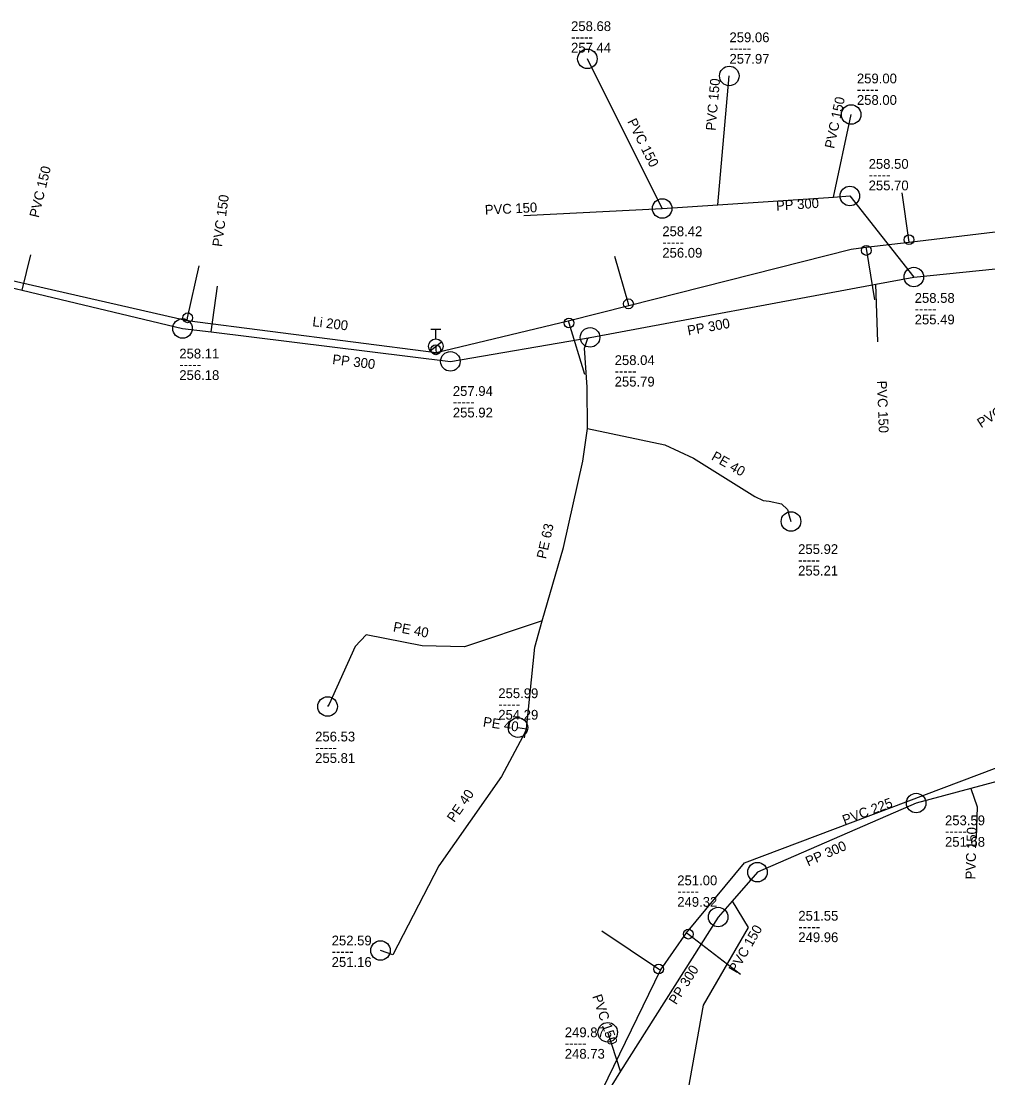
# Model space of a CAD drawing. Extents: x -771681 to -770485, y -1050143 to -1049574.
# Drawn here: x -770751.8 to -770653, y -1050034.6 to -1049926.5 of the extents above; entities that cross this region are included whole.
import ezdxf

# ---------------------------------------------------------------- set-up
doc = ezdxf.new("R2010")
doc.units = 0
doc.layers.add('Level 0', color=7, linetype='Continuous')

msp = doc.modelspace()

# ---------------------------------------------------------------- linework, layer by layer
at = {"layer": 'Level 0'}
for p, q in [((-770686.27, -1049945.68), (-770693.92, -1049930.37)), ((-770680.57, -1049945.3), (-770679.41, -1049932.12)), ((-770668.75, -1049944.51), (-770666.95, -1049936.07)), ((-770661.04, -1049948.87), (-770661.73, -1049944.09)), ((-770686.27, -1049945.68), (-770680.57, -1049945.3)), ((-770680.57, -1049945.3), (-770668.75, -1049944.51)), ((-770668.75, -1049944.51), (-770667.08, -1049944.4)), ((-770667.08, -1049944.4), (-770660.54, -1049952.69)), ((-770700.43, -1049946.39), (-770686.27, -1049945.68)), ((-770661, -1049949.12), (-770650.48, -1049947.87)), ((-770666.94, -1049949.83), (-770665.44, -1049949.65)), ((-770665.44, -1049949.65), (-770661, -1049949.12)), ((-770665.44, -1049949.65), (-770665.39, -1049949.97)), ((-770661, -1049949.12), (-770661.04, -1049948.87)), ((-770751.73, -1049954.03), (-770750.85, -1049950.41)), ((-770689.72, -1049955.43), (-770691.12, -1049950.59)), ((-770689.67, -1049955.59), (-770666.94, -1049949.83)), ((-770665.39, -1049949.97), (-770664.55, -1049955.01)), ((-770734.8, -1049956.86), (-770733.62, -1049951.55)), ((-770660.54, -1049952.69), (-770648.08, -1049951.45)), ((-770753.04, -1049952.96), (-770734.86, -1049957.12)), ((-770664.43, -1049953.41), (-770660.54, -1049952.69)), ((-770752.89, -1049953.75), (-770751.73, -1049954.03)), ((-770751.73, -1049954.03), (-770735.32, -1049957.95)), ((-770732.39, -1049958.31), (-770731.76, -1049953.63)), ((-770693.65, -1049958.86), (-770664.43, -1049953.41)), ((-770664.21, -1049959.33), (-770664.43, -1049953.41)), ((-770695.88, -1049957.16), (-770689.67, -1049955.59)), ((-770689.67, -1049955.59), (-770689.72, -1049955.43)), ((-770734.86, -1049957.12), (-770734.8, -1049956.86)), ((-770734.86, -1049957.12), (-770709.39, -1049960.4)), ((-770709.39, -1049960.4), (-770695.88, -1049957.16)), ((-770695.88, -1049957.16), (-770695.81, -1049957.39)), ((-770735.32, -1049957.95), (-770732.39, -1049958.31)), ((-770732.39, -1049958.31), (-770707.93, -1049961.32)), ((-770709.92, -1049958.02), (-770708.92, -1049958.02)), ((-770709.42, -1049959.02), (-770709.42, -1049958.02)), ((-770695.81, -1049957.39), (-770694.21, -1049962.61)), ((-770710.01, -1049960.23), (-770708.83, -1049959.31)), ((-770707.93, -1049961.32), (-770693.65, -1049958.86)), ((-770694.22, -1049959.98), (-770693.86, -1049958.95)), ((-770693.86, -1049958.95), (-770693.65, -1049958.86)), ((-770709.42, -1049959.77), (-770709.42, -1049960.13)), ((-770709.42, -1049960.13), (-770709.39, -1049960.4)), ((-770693.94, -1049963.95), (-770694.22, -1049959.98)), ((-770693.92, -1049968.17), (-770693.94, -1049963.95)), ((-770694.4, -1049971.53), (-770693.92, -1049968.17)), ((-770693.92, -1049968.17), (-770686, -1049969.86)), ((-770686, -1049969.86), (-770683.06, -1049971.22)), ((-770683.06, -1049971.22), (-770676.81, -1049975.12)), ((-770696.37, -1049980.37), (-770694.4, -1049971.53)), ((-770676.81, -1049975.12), (-770675.95, -1049975.56)), ((-770675.95, -1049975.56), (-770675.34, -1049975.63)), ((-770675.34, -1049975.63), (-770674.07, -1049975.87)), ((-770674.07, -1049975.87), (-770673.46, -1049976.46)), ((-770673.46, -1049976.46), (-770673.29, -1049977.12)), ((-770673.29, -1049977.12), (-770673.1, -1049977.69)), ((-770698.56, -1049987.85), (-770696.37, -1049980.37)), ((-770698.56, -1049987.85), (-770706.48, -1049990.52)), ((-770699.3, -1049990.55), (-770698.56, -1049987.85)), ((-770716.55, -1049989.29), (-770717.66, -1049990.48)), ((-770710.81, -1049990.4), (-770716.55, -1049989.29)), ((-770717.66, -1049990.48), (-770720.33, -1049996.37)), ((-770706.48, -1049990.52), (-770710.81, -1049990.4)), ((-770700.15, -1049998.9), (-770699.3, -1049990.55)), ((-770720.33, -1049996.37), (-770720.49, -1049996.62)), ((-770700.25, -1049999.18), (-770702.71, -1050003.76)), ((-770701.02, -1049998.77), (-770700.15, -1049998.9)), ((-770700.35, -1049999.81), (-770700.25, -1049999.18)), ((-770700.25, -1049999.18), (-770700.15, -1049998.9)), ((-770642.7, -1050001.79), (-770654.72, -1050005)), ((-770702.71, -1050003.76), (-770709.12, -1050012.92)), ((-770677.84, -1050012.6), (-770652.02, -1050002.86)), ((-770654.72, -1050005), (-770660.3, -1050006.49)), ((-770654.72, -1050005), (-770654.07, -1050006.89)), ((-770660.3, -1050006.49), (-770676.53, -1050013.56)), ((-770654.07, -1050006.89), (-770654.16, -1050010.06)), ((-770709.12, -1050012.92), (-770713.8, -1050022)), ((-770683.78, -1050019.75), (-770677.84, -1050012.6)), ((-770676.53, -1050013.56), (-770679.12, -1050016.52)), ((-770679.12, -1050016.52), (-770680.55, -1050018.15)), ((-770679.12, -1050016.52), (-770677.48, -1050019.23)), ((-770680.55, -1050018.15), (-770690.52, -1050033.93)), ((-770686.64, -1050023.47), (-770692.43, -1050019.6)), ((-770686.45, -1050023.6), (-770683.78, -1050019.75)), ((-770683.78, -1050019.75), (-770683.59, -1050019.9)), ((-770683.59, -1050019.9), (-770678.25, -1050024)), ((-770677.48, -1050019.23), (-770682.09, -1050027.16)), ((-770713.8, -1050022), (-770715.08, -1050021.57)), ((-770698.66, -1050048.72), (-770686.45, -1050023.6)), ((-770686.45, -1050023.6), (-770686.64, -1050023.47)), ((-770682.09, -1050027.16), (-770685.08, -1050043.91)), ((-770690.52, -1050033.93), (-770691.84, -1050029.94)), ((-770690.52, -1050033.93), (-770694.79, -1050040.68))]:
    msp.add_line(p, q, dxfattribs=at)
for centre, radius in [((-770693.92, -1049930.37), 1), ((-770679.41, -1049932.12), 1), ((-770666.95, -1049936.07), 1), ((-770667.08, -1049944.4), 1), ((-770686.27, -1049945.68), 1), ((-770661.04, -1049948.87), 0.5), ((-770665.39, -1049949.97), 0.5), ((-770660.54, -1049952.69), 1), ((-770689.72, -1049955.43), 0.5), ((-770735.32, -1049957.95), 1), ((-770734.8, -1049956.86), 0.5), ((-770695.81, -1049957.39), 0.5), ((-770693.65, -1049958.86), 1), ((-770709.42, -1049959.77), 0.75), ((-770709.42, -1049960.13), 0.5), ((-770707.93, -1049961.32), 1), ((-770673.1, -1049977.69), 1), ((-770720.49, -1049996.62), 1), ((-770701.02, -1049998.77), 1), ((-770660.3, -1050006.49), 1), ((-770676.53, -1050013.56), 1), ((-770680.55, -1050018.15), 1), ((-770683.59, -1050019.9), 0.5), ((-770715.08, -1050021.57), 1), ((-770686.64, -1050023.47), 0.5), ((-770691.84, -1050029.94), 1)]:
    msp.add_circle(centre, radius, dxfattribs=at)

# ---------------------------------------------------------------- texts
for s, p in [('258.68', (-770695.59, -1049927.53)), ('259.06', (-770679.39, -1049928.67)), ('-----', (-770695.59, -1049928.63)), ('257.44', (-770695.59, -1049929.73)), ('-----', (-770679.39, -1049929.77)), ('257.97', (-770679.39, -1049930.87)), ('259.00', (-770666.36, -1049932.88)), ('-----', (-770666.36, -1049933.98)), ('258.00', (-770666.36, -1049935.08)), ('258.50', (-770665.16, -1049941.62)), ('-----', (-770665.16, -1049942.72)), ('255.70', (-770665.16, -1049943.82)), ('258.42', (-770686.26, -1049948.51)), ('-----', (-770686.26, -1049949.61)), ('256.09', (-770686.26, -1049950.71)), ('258.58', (-770660.45, -1049955.33)), ('-----', (-770660.45, -1049956.43)), ('255.49', (-770660.45, -1049957.53)), ('258.11', (-770735.65, -1049961.02)), ('258.04', (-770691.13, -1049961.69)), ('-----', (-770735.65, -1049962.12)), ('256.18', (-770735.65, -1049963.22)), ('-----', (-770691.13, -1049962.79)), ('255.79', (-770691.13, -1049963.89)), ('257.94', (-770707.68, -1049964.85)), ('-----', (-770707.68, -1049965.95)), ('255.92', (-770707.68, -1049967.05)), ('255.92', (-770672.37, -1049981.02)), ('-----', (-770672.37, -1049982.12)), ('255.21', (-770672.37, -1049983.22)), ('255.99', (-770703.03, -1049995.76)), ('-----', (-770703.03, -1049996.86)), ('254.29', (-770703.03, -1049997.96)), ('256.53', (-770721.76, -1050000.19)), ('-----', (-770721.76, -1050001.29)), ('255.81', (-770721.76, -1050002.39)), ('253.59', (-770657.35, -1050008.76)), ('-----', (-770657.35, -1050009.86)), ('251.68', (-770657.35, -1050010.96)), ('251.00', (-770684.73, -1050014.9)), ('-----', (-770684.73, -1050016)), ('249.32', (-770684.73, -1050017.1)), ('251.55', (-770672.35, -1050018.52)), ('-----', (-770672.35, -1050019.62)), ('249.96', (-770672.35, -1050020.72)), ('252.59', (-770720.07, -1050021.05)), ('-----', (-770720.07, -1050022.15)), ('251.16', (-770720.07, -1050023.25)), ('249.87', (-770696.23, -1050030.44)), ('-----', (-770696.23, -1050031.54)), ('248.73', (-770696.23, -1050032.64))]:
    msp.add_text(s, height=1, dxfattribs=at).set_placement(p)
for s, rotation, p in [('PVC 150', 84.97, (-770680.82, -1049937.75)), ('PVC 150', 77.961, (-770668.69, -1049939.61)), ('PVC 150', 296.55, (-770689.86, -1049936.77)), ('PVC 150', 76.337, (-770750.03, -1049946.68)), ('PVC 150', 82.333, (-770731.29, -1049949.64)), ('PVC 150', 2.87, (-770704.38, -1049946.32)), ('PP 300', 3.824, (-770674.59, -1049945.9)), ('Li 200', 352.985, (-770722.08, -1049957.71)), ('PP 300', 10.486, (-770683.6, -1049958.67)), ('PP 300', 352.985, (-770720.04, -1049961.58)), ('PVC 150', 272.128, (-770664.31, -1049963.31)), ('PVC 150', 32.587, (-770653.66, -1049968.16)), ('PE 40', 330.484, (-770681.32, -1049971.32)), ('PE 63', 77.437, (-770698.15, -1049981.58)), ('PE 40', 349.477, (-770713.84, -1049988.92)), ('PE 40', 351.501, (-770704.64, -1049998.65)), ('PE 40', 55.175, (-770707.54, -1050008.53)), ('PVC 225', 20.668, (-770667.62, -1050008.74)), ('PVC 150', 88.374, (-770654.26, -1050014.32)), ('PP 300', 23.539, (-770671.35, -1050012.98)), ('PVC 150', 59.829, (-770678.68, -1050023.96)), ('PP 300', 57.715, (-770684.83, -1050027.19)), ('PVC 150', 288.306, (-770693.43, -1050026.25))]:
    msp.add_text(s, height=1, rotation=rotation, dxfattribs=at).set_placement(p)

doc.saveas('drawing.dxf')
